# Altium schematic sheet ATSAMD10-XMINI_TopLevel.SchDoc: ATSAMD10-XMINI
size A3; Organization: ATMEL Norway; Address1: Vestre Rosten 79; Address2: N-7075 TILLER; Address3: NORWAY; DocumentNumber: A09-2378; Revision: 2; SheetNumber: 1; SheetTotal: 3; PageSetup: Record=PageOptions¦CenterHorizontal=True¦CenterVertical=True¦PrintScale=1.01¦XCorrection=1.00¦YCorrection=1.00¦PrintKind=1¦BorderSize=5000000¦LeftOffset=0¦BottomOffset=0¦Orientation=2¦PaperLength=1000¦PaperWidth=1000¦Scale=100¦PaperSource=7¦PrintQuality=-4¦MediaType=1¦DitherType=10¦PaperKind=Letter¦PrintScaleMode=1
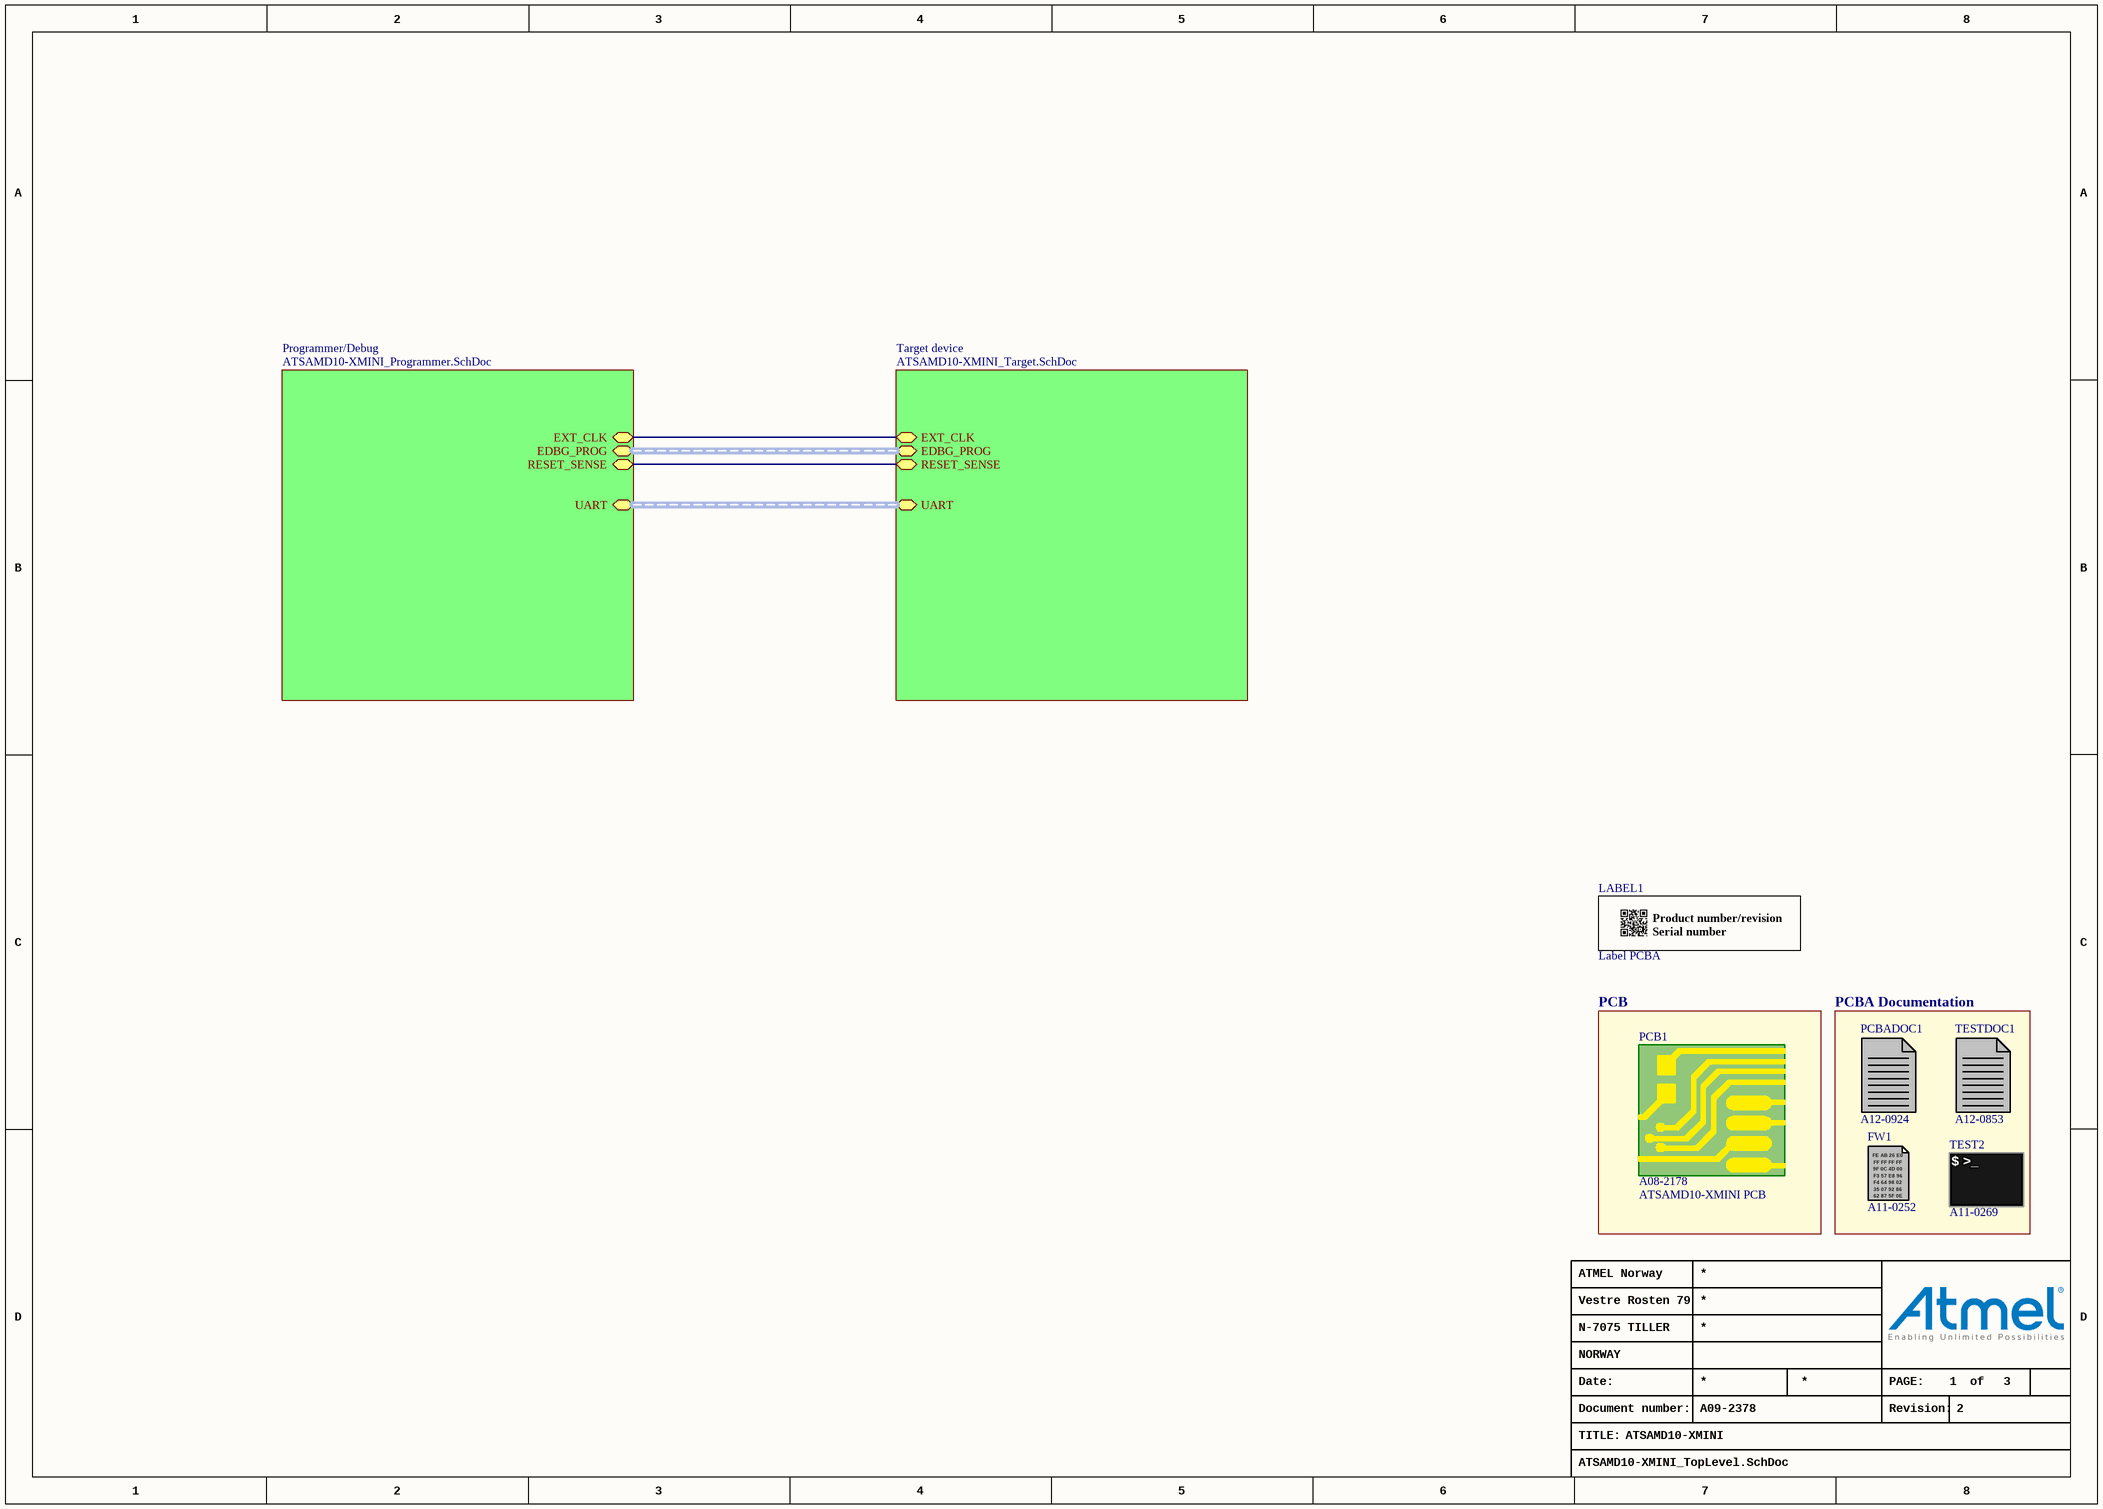
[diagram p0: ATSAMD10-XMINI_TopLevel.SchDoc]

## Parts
FW1  AN: A11-0252  (mechanical)
LABEL1  value Label PCBA  [AP8-00317]
PCB1  value ATSAMD10-XMINI PCB  AN: A08-2178  (mechanical)
PCBADOC1  AN: A12-0924  (mechanical)
TEST2  AN: A11-0269  (mechanical)
TESTDOC1  AN: A12-0853  (mechanical)

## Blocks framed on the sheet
PCB: PCB1
PCBA Documentation: FW1 PCBADOC1 TEST2 TESTDOC1

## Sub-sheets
Programmer/Debug = ATSAMD10-XMINI_Programmer.SchDoc: EXT_CLK (bidir), EDBG_PROG (harness EDBG_PROG), UART (harness UART), RESET_SENSE
Target device = ATSAMD10-XMINI_Target.SchDoc: EXT_CLK (bidir), EDBG_PROG (harness EDBG_PROG), UART (harness UART), RESET_SENSE

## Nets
(unnamed): sheet Programmer/Debug/EXT_CLK, sheet Target device/EXT_CLK
(unnamed): sheet Programmer/Debug/RESET_SENSE, sheet Target device/RESET_SENSE  [a separate net that carries the same name]

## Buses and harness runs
harness sheet Programmer/Debug/EDBG_PROG = sheet Target device/EDBG_PROG
harness sheet Programmer/Debug/UART = sheet Target device/UART

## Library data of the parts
FW1 = A11-0252: MEDBG firmware; PartGroup: Software,Firmware,Tools
LABEL1 = A09-0611: PCBA identification label PP Top White Gloss; PartGroup: Mechanical devices,Packaging materials,Printed Labels; Manufacturer: ACT Logimark AS; MPN: 505462
PCB1 = A08-2178: ATSAMD10-XMINI PCB documantation; PartGroup: Mechanical devices,Printed circuit boards
PCBADOC1 = A12-0924: ATSAMD10-XMINI PCBA documantation; PartGroup: Documentation,PCBA Documents,Atmel
TEST2 = A11-0269: Test SW for for A09-2376, ATSAMD10-XMINI; PartGroup: Software,Test software,Tools; Value: Test SW for for A09-2378
TESTDOC1 = A12-0853: Fixture Test Instructions for ATmega168-XMINI; PartGroup: Documentation,Procedures,Test Instructions; Value: Xplained Mini Test Instructions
